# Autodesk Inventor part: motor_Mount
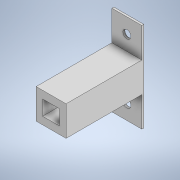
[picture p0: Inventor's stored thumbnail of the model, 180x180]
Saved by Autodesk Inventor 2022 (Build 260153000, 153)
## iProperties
Created: 2021-07
Part Number: motor_Mount
Material: Generic
Document SubType Name: Modeling
Designer: Chimms
Density: 1 g/cm^3
Appearance: Default
Author: Chimms
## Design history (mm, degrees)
sketch "Sketch1"
  geometry: L1 (0, 0)-(30, 0); L2 (30, 0)-(30, 30); L3 (30, 30)-(0, 30); L4 (0, 30)-(0, 0)
  constraints: 8 end point, 2 parallel, 1 horizontal, 1 perpendicular
  dimensions: "d0" = 30 distance of L3.end L2.end; "d1" = 30 distance of L2.end L1.end
extrude "Extrusion1" new body sketch "Sketch1" distance "d2" = 78; taper "d3" = 0 deg
sketch "Sketch2"
  geometry: L1 (0, 30)-(0, 0) reference; L2 (0, 15)-(6.5, 15); L3 (6.5, 15)-(6.5, 22.5); L4 (6.5, 22.5)-(23.5, 22.5); L5 (23.5, 22.5)-(23.5, 7.5); L6 (23.5, 7.5)-(6.5, 7.5); L7 (6.5, 7.5)-(6.5, 15)
  constraints: 12 end point, 5 perpendicular, 1 horizontal, 1 midpoint, 1 point on line
  dimensions: "d4" = 6.5 distance of L2.start L2.end; "d5" = 7.5 distance of L2.end L3.end; "d6" = 17 distance of L3.end L4.end; "d7" = 15 distance of L4.end L5.end
extrude "Extrusion2" cut sketch "Sketch2" distance "d8" = 20.166; taper "d9" = 0 deg
sketch "Sketch3"
  geometry: L1 (23.5, 7.5)-(6.5, 7.5) reference; L2 (15, 7.5)-(15, 15); C1 r 5 at (15, 15); 1 further point
  constraints: 2 end point, 1 centre point, 1 coincident, 1 midpoint, 1 vertical
  dimensions: "d10" = 7.5 distance of L2.start L2.end; "d11" = 10 diameter of C1
extrude "Extrusion3" cut sketch "Sketch3" distance "d12" = 15; taper "d13" = 0 deg
sketch "Sketch4"
  geometry: L1 (0, 0)-(-30, 0) reference; L2 (0, 0)-(-30, 0); L3 (-30, 0)-(-30, -30); L4 (-30, -30)-(0, -30); L5 (0, -30)-(0, 0); L6 (-30, 30)-(0, 30) reference; L7 (-30, 30)-(0, 30); L8 (0, 30)-(0, 60); L9 (0, 60)-(-30, 60); L10 (-30, 60)-(-30, 30); 2 further points
  constraints: 16 end point, 4 parallel, 2 horizontal, 2 perpendicular
  dimensions: "d14" = 30 distance of L4.end L3.end; "d15" = 30 distance of L3.end L2.end; "d16" = 30 distance of L9.end L8.end; "d17" = 30 distance of L8.end L7.end
extrude "Extrusion4" join sketch "Sketch4" distance "d18" = 2; taper "d19" = 0 deg
sketch "Sketch5"
  geometry: L1 (0, 0)-(30, 0) reference; L2 (15, 0)-(15, -15); L3 (30, 30)-(0, 30) reference; L4 (15, 30)-(15, 45); C1 r 4 at (15, -15); C2 r 4 at (15, 45)
  constraints: 4 end point, 2 centre point, 2 coincident, 2 midpoint, 2 vertical
  dimensions: "d20" = 15 distance of L2.start L2.end; "d21" = 8 diameter of C1; "d22" = 15 distance of L4.start L4.end; "d23" = 8 diameter of C2
extrude "Extrusion5" cut sketch "Sketch5" extent not by distance; stored distance "d24" = 0; taper "d25" = 0 deg
body "Solid1"
